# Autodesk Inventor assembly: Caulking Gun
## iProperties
Created: 2009-03
Part Number: Caulking Gun
Document SubType Name: Assembly
Designer: tangg
Mass: 1178.56 g
Surface Area: 1624.46 cm^2
Volume: 273.486 cm^3
Density: 4.30939 g/cm^3
Author: tangg
